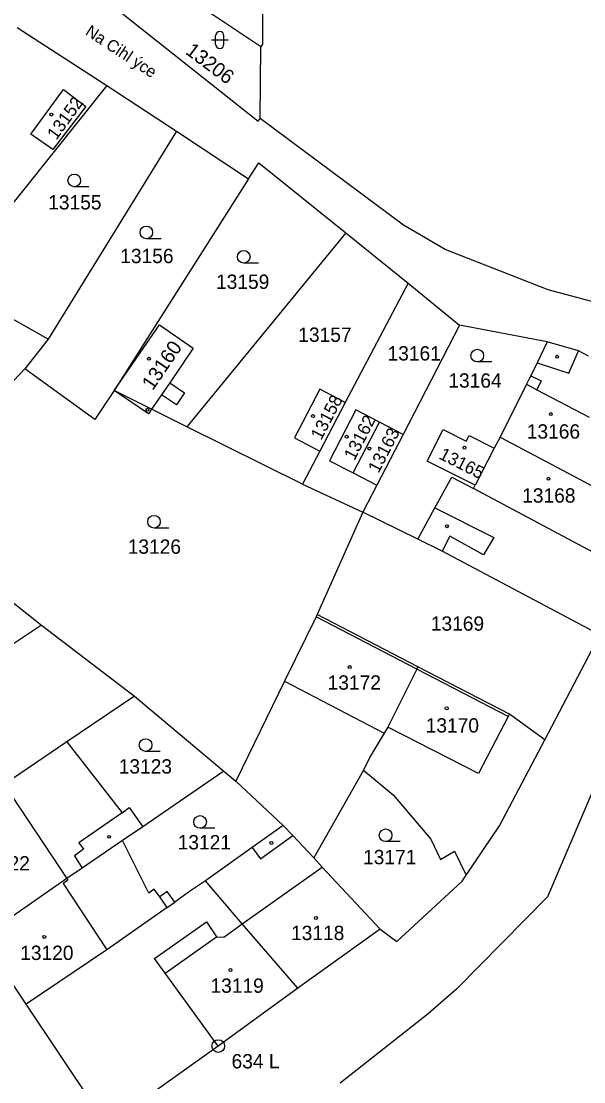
# Model space of a CAD drawing. Extents: x -822293 to -820259, y -1071573 to -1068794.
# Drawn here: x -820567.6 to -820500.9, y -1071273.6 to -1071147.9 of the extents above; entities that cross this region are included whole.
import ezdxf

# ---------------------------------------------------------------- set-up
doc = ezdxf.new("R2010")
doc.units = 0
for name, color, linetype in [('Vrstva 1', 7, 'Continuous'), ('Vrstva 10', 7, 'Continuous'), ('Vrstva 15', 7, 'Continuous'), ('Vrstva 17', 7, 'Continuous'), ('Vrstva 18', 7, 'Continuous'), ('Vrstva 19', 7, 'Continuous'), ('Vrstva 2', 7, 'Continuous'), ('Vrstva 24', 7, 'Continuous'), ('Vrstva 25', 7, 'Continuous'), ('Vrstva 3', 7, 'Continuous'), ('Vrstva 4', 7, 'Continuous')]:
    doc.layers.add(name, color=color, linetype=linetype)

msp = doc.modelspace()

# ---------------------------------------------------------------- linework, layer by layer
at = {"layer": 'Vrstva 1'}
for p, q in [((-820565.35, -1071139.3), (-820539.55, -1071159.76)), ((-820539.23, -1071150.97), (-820549, -1071144.44)), ((-820539.04, -1071145.66), (-820539.05, -1071150.66)), ((-820568.13, -1071148.68), (-820557.49, -1071155.53)), ((-820539.05, -1071150.66), (-820539.23, -1071150.97)), ((-820539.3, -1071159.45), (-820539.23, -1071150.97)), ((-820557.49, -1071155.53), (-820571.69, -1071173.31)), ((-820557.49, -1071155.53), (-820549.23, -1071160.97)), ((-820539.55, -1071159.76), (-820539.3, -1071159.45)), ((-820522.31, -1071172.09), (-820539.3, -1071159.45)), ((-820549.23, -1071160.97), (-820564.47, -1071185.62)), ((-820549.23, -1071160.97), (-820540.69, -1071166.59)), ((-820540.69, -1071166.59), (-820539.48, -1071164.69)), ((-820539.48, -1071164.69), (-820529.16, -1071173.01)), ((-820540.69, -1071166.59), (-820556.62, -1071191.69)), ((-820517.39, -1071175), (-820522.31, -1071172.09)), ((-820529.16, -1071173.01), (-820548.01, -1071195.99)), ((-820529.16, -1071173.01), (-820521.77, -1071178.96)), ((-820505.17, -1071179.75), (-820517.39, -1071175)), ((-820564.47, -1071185.62), (-820576.35, -1071178.9)), ((-820521.77, -1071178.96), (-820529.22, -1071193.13)), ((-820521.77, -1071178.96), (-820515.66, -1071183.95)), ((-820494.77, -1071182.54), (-820505.17, -1071179.75)), ((-820515.66, -1071183.95), (-820522.36, -1071196.9)), ((-820505.26, -1071185.93), (-820515.66, -1071183.95)), ((-820564.47, -1071185.62), (-820567.22, -1071189.13)), ((-820500.39, -1071187.63), (-820501.57, -1071187.01)), ((-820506.48, -1071188.41), (-820507.23, -1071189.94)), ((-820567.22, -1071189.13), (-820572.31, -1071194.51)), ((-820558.93, -1071195.12), (-820567.22, -1071189.13)), ((-820550.03, -1071190.78), (-820548.28, -1071191.96)), ((-820507.35, -1071190.17), (-820507.73, -1071190.95)), ((-820507.23, -1071189.94), (-820507.35, -1071190.17)), ((-820556.62, -1071191.69), (-820558.93, -1071195.12)), ((-820549.25, -1071193.4), (-820551.03, -1071192.21)), ((-820548.28, -1071191.96), (-820549.25, -1071193.4)), ((-820548.01, -1071195.99), (-820552.18, -1071193.91)), ((-820534.3, -1071202.8), (-820548.01, -1071195.99)), ((-820532.24, -1071198.88), (-820534.3, -1071202.8)), ((-820518.59, -1071205.59), (-820516.6, -1071201.95)), ((-820516.6, -1071201.95), (-820514.02, -1071203.33)), ((-820534.3, -1071202.8), (-820527.15, -1071206.13)), ((-820525.48, -1071202.92), (-820527.15, -1071206.13)), ((-820527.15, -1071206.13), (-820532.55, -1071218.25)), ((-820520.63, -1071209.32), (-820527.15, -1071206.13)), ((-820499.01, -1071220.67), (-820517.72, -1071210.75)), ((-820575.48, -1071211.38), (-820565.25, -1071219.52)), ((-820532.55, -1071218.25), (-820532.67, -1071218.53)), ((-820520.6, -1071224.45), (-820532.55, -1071218.25)), ((-820565.25, -1071219.52), (-820577.08, -1071227.33)), ((-820565.25, -1071219.52), (-820554.22, -1071227.91)), ((-820505.56, -1071233.12), (-820499.01, -1071220.67)), ((-820520.6, -1071224.45), (-820520.73, -1071224.72)), ((-820509.76, -1071230.08), (-820520.6, -1071224.45)), ((-820536.44, -1071226.16), (-820542.2, -1071238.02)), ((-820554.22, -1071227.91), (-820562.23, -1071233.35)), ((-820554.22, -1071227.91), (-820543.61, -1071236.82)), ((-820505.56, -1071233.12), (-820509.76, -1071230.08)), ((-820524.6, -1071232.33), (-820526.26, -1071235.07)), ((-820562.23, -1071233.35), (-820569.68, -1071238.4)), ((-820562.23, -1071233.35), (-820555.68, -1071241.74)), ((-820510.92, -1071243.31), (-820505.56, -1071233.12)), ((-820526.26, -1071235.07), (-820527.07, -1071236.71)), ((-820543.61, -1071236.82), (-820553.23, -1071243.42)), ((-820543.61, -1071236.82), (-820542.2, -1071238.02)), ((-820527.07, -1071236.71), (-820532.94, -1071247.11)), ((-820527.07, -1071236.71), (-820523.54, -1071239.61)), ((-820542.2, -1071238.02), (-820536.58, -1071243.26)), ((-820499.47, -1071238.21), (-820505.24, -1071251.73)), ((-820523.54, -1071239.61), (-820519.08, -1071244.89)), ((-820514.89, -1071249.14), (-820510.92, -1071243.31)), ((-820552.52, -1071251.26), (-820555.62, -1071245.05)), ((-820535.45, -1071244.46), (-820532.94, -1071247.11)), ((-820519.08, -1071244.89), (-820517.94, -1071247.3)), ((-820540.25, -1071245.86), (-820545.8, -1071249.8)), ((-820517.94, -1071247.3), (-820516.27, -1071246.29)), ((-820516.27, -1071246.29), (-820514.89, -1071249.14)), ((-820532.94, -1071247.11), (-820531.95, -1071248.19)), ((-820560.4, -1071248.31), (-820562.23, -1071249.55)), ((-820545.8, -1071249.8), (-820547.69, -1071251.1)), ((-820541.44, -1071254.9), (-820545.8, -1071249.8)), ((-820523.12, -1071256.99), (-820515.37, -1071249.84)), ((-820515.37, -1071249.84), (-820514.89, -1071249.14)), ((-820551.87, -1071250.81), (-820552.52, -1071251.26)), ((-820551.22, -1071251.72), (-820551.87, -1071250.81)), ((-820550.32, -1071251.09), (-820551.22, -1071251.72)), ((-820549.44, -1071252.34), (-820550.32, -1071251.09)), ((-820547.69, -1071251.1), (-820549.44, -1071252.34)), ((-820550.34, -1071252.97), (-820549.44, -1071252.34)), ((-820505.24, -1071251.73), (-820515.99, -1071262.62)), ((-820550.34, -1071252.97), (-820557.48, -1071258)), ((-820525.08, -1071255.54), (-820523.12, -1071256.99)), ((-820515.99, -1071262.62), (-820519.39, -1071265.59)), ((-820558.89, -1071276.65), (-820567.06, -1071264.43)), ((-820519.39, -1071265.59), (-820529.82, -1071273.81)), ((-820544.28, -1071269.4), (-820555.99, -1071277.72))]:
    msp.add_line(p, q, dxfattribs=at)
at = {"layer": 'Vrstva 10'}
msp.add_spline([(-820648.37, -1071145.75), (-820635.21, -1071175.92), (-820619.77, -1071208), (-820606.88, -1071231.72), (-820592.84, -1071254.92), (-820557.31, -1071306.48), (-820522.72, -1071349.67), (-820487.72, -1071388.36), (-820440.04, -1071434.15), (-820382.01, -1071481.32), (-820258.78, -1071573.12)], degree=3, dxfattribs=at)
at = {"layer": 'Vrstva 2'}
for p, q in [((-820566.49, -1071161.32), (-820562.65, -1071156.02)), ((-820562.65, -1071156.02), (-820559.99, -1071158.04)), ((-820559.99, -1071158.04), (-820563.89, -1071163.14)), ((-820563.89, -1071163.14), (-820566.49, -1071161.32)), ((-820556.62, -1071191.69), (-820551.25, -1071183.92)), ((-820551.25, -1071183.92), (-820547.24, -1071186.66)), ((-820505.26, -1071185.93), (-820506.48, -1071188.41)), ((-820501.57, -1071187.01), (-820505.26, -1071185.93)), ((-820547.24, -1071186.66), (-820550.03, -1071190.78)), ((-820507.73, -1071190.95), (-820510.83, -1071197.24)), ((-820552.18, -1071193.91), (-820556.62, -1071191.69)), ((-820551.03, -1071192.21), (-820552.18, -1071193.91)), ((-820532.23, -1071191.54), (-820535.25, -1071197.3)), ((-820529.22, -1071193.13), (-820532.23, -1071191.54)), ((-820529.22, -1071193.13), (-820532.24, -1071198.88)), ((-820527.96, -1071194), (-820531.08, -1071200.02)), ((-820525.16, -1071195.45), (-820527.96, -1071194)), ((-820528.28, -1071201.47), (-820525.16, -1071195.45)), ((-820522.36, -1071196.9), (-820525.16, -1071195.45)), ((-820535.25, -1071197.3), (-820532.24, -1071198.88)), ((-820522.36, -1071196.9), (-820525.48, -1071202.92)), ((-820519.5, -1071200.07), (-820517.6, -1071196.32)), ((-820517.6, -1071196.32), (-820514.87, -1071197.71)), ((-820514.87, -1071197.71), (-820514.53, -1071197.03)), ((-820514.53, -1071197.03), (-820511.58, -1071198.53)), ((-820510.83, -1071197.24), (-820511.58, -1071198.53)), ((-820510.83, -1071197.24), (-820496.66, -1071204.76)), ((-820511.58, -1071198.53), (-820513.82, -1071202.93)), ((-820531.08, -1071200.02), (-820528.28, -1071201.47)), ((-820513.82, -1071202.93), (-820519.5, -1071200.07)), ((-820528.28, -1071201.47), (-820525.48, -1071202.92)), ((-820514.02, -1071203.33), (-820513.82, -1071202.93)), ((-820520.63, -1071209.32), (-820518.59, -1071205.59)), ((-820517.72, -1071210.75), (-820520.63, -1071209.32)), ((-820532.67, -1071218.53), (-820536.44, -1071226.16)), ((-820520.73, -1071224.72), (-820524.17, -1071231.61)), ((-820524.17, -1071231.61), (-820524.6, -1071232.33)), ((-820555.68, -1071241.74), (-820554.83, -1071241.14)), ((-820554.83, -1071241.14), (-820553.23, -1071243.42)), ((-820553.23, -1071243.42), (-820555.62, -1071245.05)), ((-820536.58, -1071243.26), (-820540.25, -1071245.86)), ((-820536.58, -1071243.26), (-820535.45, -1071244.46)), ((-820555.62, -1071245.05), (-820560.4, -1071248.31)), ((-820531.95, -1071248.19), (-820525.08, -1071255.54)), ((-820562.23, -1071249.55), (-820572.35, -1071256.57)), ((-820534.83, -1071262.53), (-820541.44, -1071254.9)), ((-820525.08, -1071255.54), (-820534.83, -1071262.53)), ((-820567.06, -1071264.43), (-820572.35, -1071256.57)), ((-820557.48, -1071258), (-820567.06, -1071264.43)), ((-820534.83, -1071262.53), (-820544.28, -1071269.4))]:
    msp.add_line(p, q, dxfattribs=at)
at = {"layer": 'Vrstva 24'}
for radius in [0.75, 0.0327]:
    msp.add_circle((-820544.28, -1071269.4), radius, dxfattribs=at)
at = {"layer": 'Vrstva 25'}
for p, q in [((-820545.1, -1071150.14), (-820543.1, -1071150.14)), ((-820544.6, -1071150.64), (-820544.6, -1071149.64)), ((-820543.6, -1071150.64), (-820543.6, -1071149.64)), ((-820559.61, -1071167.55), (-820561.36, -1071167.55)), ((-820551.06, -1071173.71), (-820552.81, -1071173.71)), ((-820539.51, -1071176.6), (-820541.26, -1071176.6)), ((-820511.82, -1071188.31), (-820513.57, -1071188.31)), ((-820550.15, -1071208), (-820551.9, -1071208)), ((-820551.15, -1071234.48), (-820552.9, -1071234.48)), ((-820544.68, -1071243.59), (-820546.43, -1071243.59)), ((-820522.69, -1071245.17), (-820524.44, -1071245.17))]:
    msp.add_line(p, q, dxfattribs=at)
for centre, radius in [((-820564.06, -1071158.99), 0.175), ((-820561.36, -1071166.8), 0.75), ((-820552.81, -1071172.96), 0.75), ((-820541.26, -1071175.85), 0.75), ((-820513.57, -1071187.56), 0.75), ((-820552.5, -1071187.93), 0.175), ((-820504.09, -1071187.7), 0.175), ((-820552.68, -1071193.98), 0.175), ((-820533.04, -1071194.73), 0.175), ((-820504.84, -1071194.49), 0.175), ((-820529.05, -1071197.18), 0.175), ((-820526.35, -1071198.58), 0.175), ((-820515.08, -1071198.47), 0.175), ((-820505.12, -1071202.16), 0.175), ((-820551.9, -1071207.25), 0.75), ((-820517.17, -1071207.78), 0.175), ((-820528.68, -1071224.48), 0.175), ((-820517.19, -1071229.37), 0.175), ((-820552.9, -1071233.73), 0.75), ((-820546.43, -1071242.84), 0.75), ((-820524.44, -1071244.42), 0.75), ((-820557.22, -1071244.6), 0.175), ((-820537.98, -1071245.33), 0.175), ((-820532.7, -1071254.22), 0.175), ((-820564.91, -1071256.46), 0.175), ((-820542.83, -1071260.39), 0.175)]:
    msp.add_circle(centre, radius, dxfattribs=at)
for centre, start, end in [((-820544.1, -1071149.64), 0, 180), ((-820544.1, -1071150.64), 180, 0)]:
    msp.add_arc(centre, 0.5, start, end, dxfattribs=at)
at = {"layer": 'Vrstva 3'}
for p, q in [((-820502.72, -1071189.64), (-820501.57, -1071187.01)), ((-820506.48, -1071188.41), (-820502.72, -1071189.64)), ((-820550.03, -1071190.78), (-820551.03, -1071192.21)), ((-820507.73, -1071190.95), (-820506.49, -1071191.6)), ((-820552.54, -1071194.45), (-820556.62, -1071191.69)), ((-820506.49, -1071191.6), (-820500.3, -1071194.85)), ((-820552.18, -1071193.91), (-820552.54, -1071194.45)), ((-820499.85, -1071210.87), (-820514.02, -1071203.33)), ((-820518.59, -1071205.59), (-820511.6, -1071209.12)), ((-820516.81, -1071208.97), (-820517.72, -1071210.75)), ((-820512.84, -1071211.16), (-820516.81, -1071208.97)), ((-820511.6, -1071209.12), (-820512.84, -1071211.16)), ((-820520.73, -1071224.72), (-820532.67, -1071218.53)), ((-820509.9, -1071230.35), (-820520.73, -1071224.72)), ((-820536.44, -1071226.16), (-820524.6, -1071232.33)), ((-820509.9, -1071230.35), (-820513.4, -1071237.1)), ((-820513.4, -1071237.1), (-820524.17, -1071231.61)), ((-820569.68, -1071238.4), (-820562.23, -1071249.55)), ((-820555.68, -1071241.74), (-820560.8, -1071245.32)), ((-820539.27, -1071247.22), (-820535.45, -1071244.46)), ((-820560.28, -1071246.06), (-820561.32, -1071246.87)), ((-820560.8, -1071245.32), (-820560.28, -1071246.06)), ((-820540.25, -1071245.86), (-820539.27, -1071247.22)), ((-820561.32, -1071246.87), (-820560.4, -1071248.31)), ((-820541.44, -1071254.9), (-820531.95, -1071248.19)), ((-820562.1, -1071249.74), (-820562.68, -1071250.14)), ((-820562.68, -1071250.14), (-820557.48, -1071258)), ((-820562.23, -1071249.55), (-820562.1, -1071249.74)), ((-820543.62, -1071256.51), (-820541.44, -1071254.9)), ((-820550.56, -1071260.76), (-820544.47, -1071256.44)), ((-820544.47, -1071256.44), (-820543.62, -1071256.51)), ((-820544.28, -1071269.4), (-820550.56, -1071260.76))]:
    msp.add_line(p, q, dxfattribs=at)
at = {"layer": 'Vrstva 4'}
for p, q in [((-820507.23, -1071189.94), (-820505.98, -1071190.56)), ((-820505.98, -1071190.56), (-820506.49, -1071191.6)), ((-820509.76, -1071230.08), (-820509.9, -1071230.35)), ((-820550.34, -1071252.97), (-820551.22, -1071251.72)), ((-820551.83, -1071259.02), (-820545.68, -1071254.67)), ((-820545.68, -1071254.67), (-820544.47, -1071256.44)), ((-820550.56, -1071260.76), (-820551.83, -1071259.02))]:
    msp.add_line(p, q, dxfattribs=at)

# ---------------------------------------------------------------- texts
at = {"layer": 'Vrstva 15'}
msp.add_text('Na Cihl\xa0ýce', height=1.4, rotation=326.63556, dxfattribs=at).set_placement((-820560.157, -1071149.444))
at = {"layer": 'Vrstva 17'}
msp.add_text('634 L', height=1.7, dxfattribs=at).set_placement((-820542.703, -1071272.05))
at = {"layer": 'Vrstva 18'}
msp.add_text('13206', height=1.7, rotation=323.18639, dxfattribs=at).set_placement((-820548.282, -1071151.702))
for s, p in [('13155', (-820564.446, -1071170.24)), ('13156', (-820555.905, -1071176.6)), ('13159', (-820544.545, -1071179.65)), ('13164', (-820516.994, -1071191.36)), ('13126', (-820555.018, -1071211.05)), ('13123', (-820556.086, -1071237.1)), ('13121', (-820549.092, -1071246.09)), ('13171', (-820527.111, -1071247.85))]:
    msp.add_text(s, height=1.7, dxfattribs=at).set_placement(p)
at = {"layer": 'Vrstva 19'}
for s, height, rotation, p in [('13152', 1.5, 54.07686, (-820563.482, -1071162.09)), ('13160', 1.7, 55.74591, (-820552.052, -1071191.779)), ('13158', 1.5, 62.26839, (-820532.077, -1071197.671)), ('13162', 1.5, 62.61372, (-820528.127, -1071200.076)), ('13163', 1.5, 62.61372, (-820525.271, -1071201.584)), ('13165', 1.5, 333.26487, (-820518.221, -1071199.728))]:
    msp.add_text(s, height=height, rotation=rotation, dxfattribs=at).set_placement(p)
for s, p in [('13157', (-820534.79, -1071185.93)), ('13161', (-820524.206, -1071188.14)), ('13166', (-820507.694, -1071197.4)), ('13168', (-820508.237, -1071204.99)), ('13169', (-820519.074, -1071220.17)), ('13172', (-820531.313, -1071227.16)), ('13170', (-820519.682, -1071232.24)), ('13122', (-820572.944, -1071248.59)), ('13118', (-820535.65, -1071256.84)), ('13120', (-820567.772, -1071259.2)), ('13119', (-820545.206, -1071263.09))]:
    msp.add_text(s, height=1.7, dxfattribs=at).set_placement(p)

doc.saveas('drawing.dxf')
